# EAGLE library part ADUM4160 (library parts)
Triple-Channel Digital Isolators Source: http://www.analog.com/static/imported-files/data_sheets/ADuM1300_1301.pdf
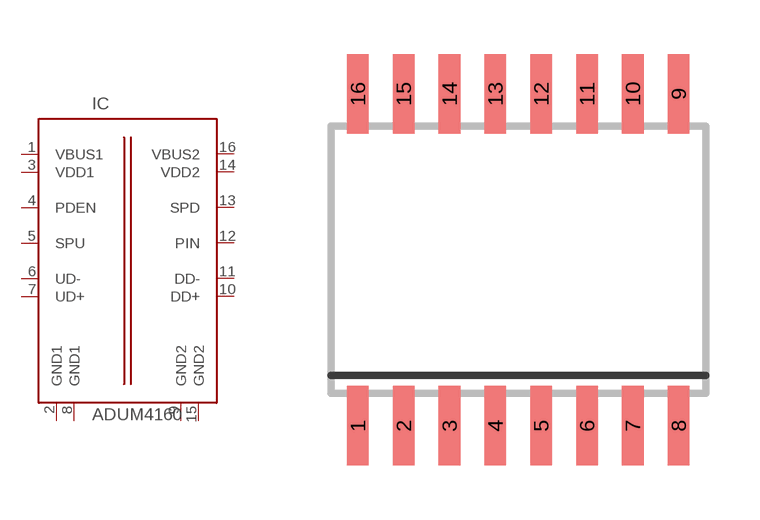
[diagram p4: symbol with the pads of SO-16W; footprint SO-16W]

Designator prefix IC

## ADUM4160  [SO-16W]
1  VBUS1  in
2  GND1  in
3  VDD1  in
4  PDEN  in
5  SPU  in
6  UD-  nc
7  UD+  nc
8  GND1  in
9  GND2  in
10  DD+  in
11  DD-  nc
12  PIN  hiz
13  SPD  hiz
14  VDD2  hiz
15  GND2  in
16  VBUS2  in

## Footprint SO-16W (pad centres in mm)
16-Lead (Wide Body) Small Outline Package (R-16) Source: http://www.analog.com/UploadedFiles/Data_Sheets/409317160AD421_c.pdf
smd 0.6 x 2.2: 1 -4.445,-4.6; 2 -3.175,-4.6; 3 -1.905,-4.6; 4 -0.635,-4.6; 5 0.635,-4.6; 6 1.905,-4.6; 7 3.175,-4.6; 8 4.445,-4.6; 9 4.445,4.6; 10 3.175,4.6; 11 1.905,4.6; 12 0.635,4.6; 13 -0.635,4.6; 14 -1.905,4.6; 15 -3.175,4.6; 16 -4.445,4.6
